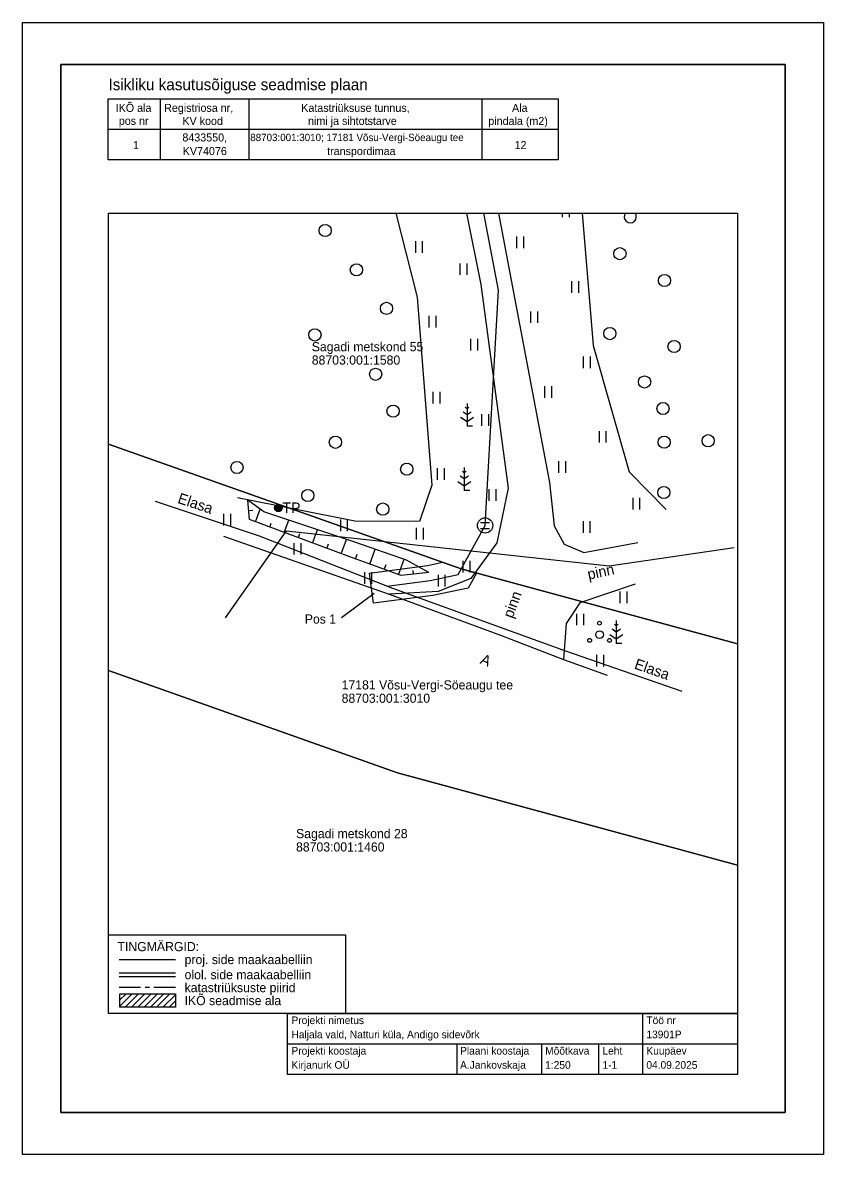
# Model space of a CAD drawing. Extents: x 614509.3 to 614561.8, y 6610581.6 to 6610655.9.
import ezdxf

# ---------------------------------------------------------------- set-up
doc = ezdxf.new("R2010")
doc.units = 0
for name, color, linetype in [('HALJASTUS', 7, 'Continuous'), ('KASUTUSALA', 7, 'Continuous'), ('KPKAABEL', 7, 'Continuous'), ('PIIR', 7, 'Continuous'), ('POST', 7, 'Continuous'), ('PR_SIDE', 7, 'Continuous'), ('PUU', 7, 'Continuous'), ('RELJEEF', 7, 'Continuous'), ('SITRASS', 7, 'Continuous'), ('TEE', 7, 'Continuous'), ('VORMISTUS', 7, 'Continuous')]:
    doc.layers.add(name, color=color, linetype=linetype)

msp = doc.modelspace()

# ---------------------------------------------------------------- linework, layer by layer
at = {"layer": 'HALJASTUS'}
for p, q in [((614544.692, 6610643.359), (614544.692, 6610643.095)), ((614545.148, 6610643.359), (614545.148, 6610643.095)), ((614541.699, 6610641.831), (614541.699, 6610641.07)), ((614542.154, 6610641.831), (614542.154, 6610641.07)), ((614535.06, 6610641.522), (614535.06, 6610640.761)), ((614535.515, 6610641.522), (614535.515, 6610640.761)), ((614537.97, 6610640.066), (614537.97, 6610639.305)), ((614538.425, 6610640.066), (614538.425, 6610639.305)), ((614545.305, 6610638.894), (614545.305, 6610638.133)), ((614545.76, 6610638.894), (614545.76, 6610638.133)), ((614535.944, 6610636.621), (614535.944, 6610635.859)), ((614536.399, 6610636.621), (614536.399, 6610635.859)), ((614542.616, 6610636.916), (614542.616, 6610636.154)), ((614543.071, 6610636.916), (614543.071, 6610636.154)), ((614538.683, 6610635.117), (614538.683, 6610634.356)), ((614539.138, 6610635.117), (614539.138, 6610634.356)), ((614546.066, 6610633.956), (614546.066, 6610633.195)), ((614546.522, 6610633.956), (614546.522, 6610633.195)), ((614543.533, 6610632), (614543.533, 6610631.239)), ((614543.988, 6610632), (614543.988, 6610631.239)), ((614536.214, 6610631.628), (614536.214, 6610630.867)), ((614536.669, 6610631.628), (614536.669, 6610630.867)), ((614539.396, 6610630.168), (614539.396, 6610629.407)), ((614539.851, 6610630.168), (614539.851, 6610629.407)), ((614547.102, 6610629.065), (614547.102, 6610628.304)), ((614547.557, 6610629.065), (614547.557, 6610628.304)), ((614544.45, 6610627.085), (614544.45, 6610626.324)), ((614544.905, 6610627.085), (614544.905, 6610626.324)), ((614536.484, 6610626.635), (614536.484, 6610625.874)), ((614536.94, 6610626.635), (614536.94, 6610625.874)), ((614539.884, 6610625.242), (614539.884, 6610624.481)), ((614540.339, 6610625.242), (614540.339, 6610624.481)), ((614549.31, 6610624.677), (614549.31, 6610623.916)), ((614549.765, 6610624.677), (614549.765, 6610623.916)), ((614522.483, 6610623.638), (614522.483, 6610622.877)), ((614522.938, 6610623.638), (614522.938, 6610622.877)), ((614530.144, 6610623.259), (614530.144, 6610622.498)), ((614530.599, 6610623.259), (614530.599, 6610622.498)), ((614546.054, 6610623.15), (614546.054, 6610622.388)), ((614546.509, 6610623.15), (614546.509, 6610622.388)), ((614535.114, 6610622.711), (614535.114, 6610621.95)), ((614535.569, 6610622.711), (614535.569, 6610621.95)), ((614527.1, 6610621.719), (614527.1, 6610620.958)), ((614527.555, 6610621.719), (614527.555, 6610620.958)), ((614538.169, 6610620.546), (614538.169, 6610619.785)), ((614538.624, 6610620.546), (614538.624, 6610619.785)), ((614531.717, 6610619.801), (614531.717, 6610619.04)), ((614532.173, 6610619.801), (614532.173, 6610619.04)), ((614536.546, 6610619.624), (614536.546, 6610618.863)), ((614537.001, 6610619.624), (614537.001, 6610618.863)), ((614548.468, 6610618.528), (614548.468, 6610617.767)), ((614548.923, 6610618.528), (614548.923, 6610617.767)), ((614545.619, 6610617.083), (614545.619, 6610616.322)), ((614546.074, 6610617.083), (614546.074, 6610616.322)), ((614546.943, 6610614.379), (614546.943, 6610613.618)), ((614547.398, 6610614.379), (614547.398, 6610613.618))]:
    msp.add_line(p, q, dxfattribs=at)
for points in [[(614533.79, 6610643.359), (614535.178, 6610637.844), (614536.147, 6610625.508), (614535.327, 6610623.128), (614531.09, 6610623.152), (614523.405, 6610624.686)], [(614545.994, 6610643.359), (614546.728, 6610634.687), (614549.085, 6610626.386), (614551.511, 6610623.921)]]:
    msp.add_lwpolyline(points, dxfattribs=at)
for centre in [(614529.149, 6610642.22), (614548.472, 6610640.703), (614531.193, 6610639.642), (614551.397, 6610638.941), (614533.163, 6610637.113), (614528.476, 6610635.372), (614547.809, 6610635.459), (614552.024, 6610634.614), (614532.454, 6610632.788), (614550.091, 6610632.284), (614533.599, 6610630.37), (614551.296, 6610630.541), (614529.818, 6610628.329), (614551.372, 6610628.334), (614554.261, 6610628.43), (614523.363, 6610626.673), (614534.495, 6610626.562), (614551.351, 6610625.033), (614528.012, 6610624.834), (614532.922, 6610623.945)]:
    msp.add_circle(centre, 0.4, dxfattribs=at)
msp.add_arc((614549.15, 6610643.122), 0.4, 143.55708, 36.44292, dxfattribs=at)
at = {"layer": 'KASUTUSALA'}
msp.add_lwpolyline([(614538.517, 6610618.758), (614536.198, 6610618.276), (614533.312, 6610617.897), (614532.321, 6610617.767), (614532.061, 6610619.75), (614535.864, 6610620.249), (614536.84, 6610620.452), (614538.06, 6610620.02), (614539.06, 6610619.749)], close=True, dxfattribs=at)
at = {"layer": 'KPKAABEL'}
msp.add_lwpolyline([(614522.611, 6610616.817), (614526.609, 6610622.512), (614547.773, 6610620.23), (614555.956, 6610621.423)], dxfattribs=at)
at = {"layer": 'PIIR'}
for points in [[(614514.935, 6610628.206), (614538.06, 6610620.02), (614556.185, 6610615.099)], [(614556.185, 6610615.099), (614538.06, 6610620.02), (614514.935, 6610628.206)], [(614556.185, 6610600.589), (614533.88, 6610606.64), (614514.935, 6610613.353)], [(614514.935, 6610613.353), (614533.88, 6610606.64), (614556.185, 6610600.589)]]:
    msp.add_lwpolyline(points, dxfattribs=at)
at = {"layer": 'POST'}
for radius in [0.25, 0.225, 0.2, 0.175, 0.15, 0.125, 0.1, 0.075, 0.05, 0.025]:
    msp.add_circle((614526.078, 6610624.026), radius, dxfattribs=at)
at = {"layer": 'PR_SIDE'}
for p, q in [((614539.339, 6610623.071), (614539.92, 6610623.071)), ((614539.339, 6610622.671), (614539.92, 6610622.671))]:
    msp.add_line(p, q, dxfattribs=at)
for points in [[(614539.63, 6610622.871), (614540.501, 6610638.302), (614539.551, 6610643.359)], [(614533.183, 6610618.889), (614536.031, 6610619.263), (614537.862, 6610619.644), (614539.63, 6610622.871)]]:
    msp.add_lwpolyline(points, dxfattribs=at)
msp.add_circle((614539.63, 6610622.871), 0.5, dxfattribs=at)
at = {"layer": 'PUU'}
for p, q in [((614538.452, 6610630.531), (614538.327, 6610630.614)), ((614538.452, 6610630.881), (614538.452, 6610629.381)), ((614538.576, 6610630.614), (614538.452, 6610630.531)), ((614538.027, 6610629.97), (614538.452, 6610629.688)), ((614538.452, 6610630.131), (614538.185, 6610630.309)), ((614538.718, 6610630.309), (614538.452, 6610630.131)), ((614538.452, 6610629.688), (614538.876, 6610629.97)), ((614538.812, 6610629.381), (614538.452, 6610629.381)), ((614538.268, 6610625.919), (614538.001, 6610626.097)), ((614538.268, 6610626.319), (614538.143, 6610626.402)), ((614538.268, 6610626.669), (614538.268, 6610625.169)), ((614538.392, 6610626.402), (614538.268, 6610626.319)), ((614538.534, 6610626.097), (614538.268, 6610625.919)), ((614537.844, 6610625.759), (614538.268, 6610625.476)), ((614538.268, 6610625.476), (614538.692, 6610625.759)), ((614538.628, 6610625.169), (614538.268, 6610625.169)), ((614548.234, 6610616.28), (614548.109, 6610616.363)), ((614548.234, 6610616.63), (614548.234, 6610615.13)), ((614548.358, 6610616.363), (614548.234, 6610616.28)), ((614547.81, 6610615.719), (614548.234, 6610615.436)), ((614548.234, 6610615.88), (614547.967, 6610616.058)), ((614548.5, 6610616.058), (614548.234, 6610615.88)), ((614548.234, 6610615.436), (614548.658, 6610615.719)), ((614548.594, 6610615.13), (614548.234, 6610615.13))]:
    msp.add_line(p, q, dxfattribs=at)
for centre, radius in [((614547.137, 6610616.456), 0.125), ((614547.137, 6610615.706), 0.25), ((614546.487, 6610615.331), 0.125), ((614547.787, 6610615.331), 0.125)]:
    msp.add_circle(centre, radius, dxfattribs=at)
at = {"layer": 'RELJEEF'}
for p, q in [((614524.138, 6610623.849), (614524.397, 6610623.874)), ((614524.578, 6610623.117), (614524.887, 6610623.944)), ((614526.451, 6610622.416), (614526.755, 6610623.228)), ((614525.514, 6610622.766), (614525.612, 6610623.026)), ((614527.387, 6610622.065), (614527.493, 6610622.347)), ((614528.323, 6610621.714), (614528.653, 6610622.593)), ((614529.26, 6610621.363), (614529.374, 6610621.667)), ((614530.196, 6610621.012), (614530.55, 6610621.957)), ((614531.134, 6610620.665), (614531.252, 6610620.99)), ((614532.074, 6610620.324), (614532.432, 6610621.311)), ((614533.014, 6610619.983), (614533.135, 6610620.317)), ((614533.954, 6610619.642), (614534.322, 6610620.656)), ((614534.938, 6610619.679), (614534.911, 6610619.916))]:
    msp.add_line(p, q, dxfattribs=at)
for points in [[(614535.932, 6610619.794), (614534.118, 6610619.583), (614530.754, 6610620.804), (614524.195, 6610623.26), (614524.073, 6610624.528)], [(614535.932, 6610619.794), (614534.474, 6610620.604), (614531.094, 6610621.775), (614525.123, 6610623.775), (614524.073, 6610624.528)]]:
    msp.add_lwpolyline(points, dxfattribs=at)
at = {"layer": 'SITRASS'}
msp.add_lwpolyline([(614517.998, 6610624.454), (614524.809, 6610622.188), (614533.561, 6610618.749), (614544.841, 6610614.658), (614552.54, 6610611.993)], dxfattribs=at)
at = {"layer": 'TEE'}
for points in [[(614538.422, 6610643.359), (614539.358, 6610638.689), (614541.15, 6610625.313), (614540.399, 6610621.73), (614538.7, 6610619.389), (614536.555, 6610618.536), (614533.332, 6610618.365)], [(614540.506, 6610643.359), (614541.344, 6610638.973), (614543.859, 6610625.699), (614544.165, 6610622.854), (614544.82, 6610621.644), (614546.108, 6610621.086), (614549.656, 6610621.758)], [(614522.483, 6610622.159), (614533.332, 6610618.365), (614540.635, 6610615.665), (614544.772, 6610614.069), (614547.635, 6610613.055)], [(614549.48, 6610619.026), (614545.854, 6610617.789), (614544.938, 6610616.449), (614544.772, 6610614.069)]]:
    msp.add_lwpolyline(points, dxfattribs=at)
at = {"layer": 'VORMISTUS'}
for p, q in [((614518.322, 6610650.864), (614518.322, 6610646.864)), ((614524.147, 6610650.864), (614524.147, 6610646.864)), ((614539.422, 6610650.864), (614539.422, 6610646.864)), ((614514.922, 6610648.864), (614544.422, 6610648.864)), ((614532.367, 6610618.407), (614530.207, 6610616.81)), ((614515.636, 6610594.392), (614519.33, 6610594.392)), ((614515.636, 6610593.511), (614519.33, 6610593.511)), ((614515.636, 6610593.289), (614519.33, 6610593.289)), ((614517.046, 6610592.55), (614515.635, 6610592.55)), ((614516.499, 6610592.137), (614515.689, 6610591.327)), ((614516.087, 6610592.137), (614515.689, 6610591.739)), ((614516.911, 6610592.137), (614516.037, 6610591.263)), ((614517.323, 6610592.137), (614516.449, 6610591.263)), ((614517.735, 6610592.137), (614516.861, 6610591.263)), ((614518.146, 6610592.137), (614517.273, 6610591.263)), ((614517.628, 6610592.55), (614517.337, 6610592.55)), ((614518.558, 6610592.137), (614517.685, 6610591.263)), ((614519.33, 6610592.55), (614517.919, 6610592.55)), ((614518.97, 6610592.137), (614518.096, 6610591.263)), ((614519.33, 6610592.085), (614518.508, 6610591.263)), ((614519.33, 6610591.673), (614518.92, 6610591.263)), ((614549.958, 6610590.859), (614549.958, 6610588.859)), ((614526.685, 6610588.859), (614556.185, 6610588.859)), ((614537.779, 6610588.859), (614537.779, 6610586.859)), ((614543.322, 6610588.859), (614543.322, 6610586.859)), ((614547.074, 6610588.859), (614547.074, 6610586.859)), ((614549.958, 6610588.859), (614549.958, 6610586.859))]:
    msp.add_line(p, q, dxfattribs=at)
for points in [[(614509.31, 6610655.859), (614561.81, 6610655.859), (614561.81, 6610581.609), (614509.31, 6610581.609)], [(614511.81, 6610584.359), (614559.31, 6610584.359), (614559.31, 6610653.109), (614511.81, 6610653.109)], [(614511.81, 6610653.109), (614559.31, 6610653.109), (614559.31, 6610584.359), (614511.81, 6610584.359)], [(614514.922, 6610650.864), (614544.422, 6610650.864), (614544.422, 6610646.864), (614514.922, 6610646.864)], [(614556.185, 6610590.859), (614514.935, 6610590.859), (614514.935, 6610643.359), (614556.185, 6610643.359)], [(614514.93, 6610590.85), (614514.93, 6610596.002), (614530.47, 6610596.002), (614530.47, 6610590.85)], [(614515.689, 6610592.137), (614519.33, 6610592.137), (614519.33, 6610591.263), (614515.689, 6610591.263)], [(614526.685, 6610590.859), (614556.185, 6610590.859), (614556.185, 6610586.859), (614526.685, 6610586.859)]]:
    msp.add_lwpolyline(points, close=True, dxfattribs=at)

# ---------------------------------------------------------------- texts
at = {"layer": 'PIIR'}
for s, p in [('Sagadi metskond 55', (614528.267, 6610634.298)), ('88703:001:1580', (614528.267, 6610633.423)), ('17181 Võsu-Vergi-Söeaugu tee', (614530.225, 6610612.11)), ('88703:001:3010', (614530.225, 6610611.235)), ('Sagadi metskond 28', (614527.236, 6610602.354)), ('88703:001:1460', (614527.236, 6610601.479))]:
    msp.add_text(s, height=0.6, dxfattribs=at).set_placement(p)
at = {"layer": 'POST'}
msp.add_text(' TP', height=0.7, dxfattribs=at).set_placement((614526.078, 6610623.677))
at = {"layer": 'SITRASS'}
for rotation, p in [(341.61835, (614519.423, 6610624.36)), (340.86305, (614549.363, 6610613.495))]:
    msp.add_text('Elasa', height=0.7, rotation=rotation, dxfattribs=at).set_placement(p)
at = {"layer": 'TEE'}
for s, rotation, p in [('pinn', 12.10958, (614546.423, 6610619.308)), ('pinn', 69.86402, (614541.436, 6610616.737)), ('A', 336.74443, (614539.256, 6610613.834))]:
    msp.add_text(s, height=0.7, rotation=rotation, dxfattribs=at).set_placement(p)
at = {"layer": 'VORMISTUS'}
for s, height, p in [('Isikliku kasutusõiguse seadmise plaan', 0.75, (614514.938, 6610651.427)), ('IKÕ ala', 0.525, (614515.411, 6610650.005)), ('Registriosa nr,', 0.525, (614518.59, 6610650.005)), ('Katastriüksuse tunnus,', 0.525, (614527.58, 6610650.005)), ('Ala', 0.525, (614541.401, 6610650.005)), ('pos nr', 0.525, (614515.616, 6610649.154)), ('KV kood', 0.525, (614519.787, 6610649.146)), ('nimi ja sihtotstarve', 0.525, (614528.025, 6610649.15)), ('pindala (m2)', 0.525, (614539.845, 6610649.146)), ('8433550,', 0.525, (614519.785, 6610648.064)), ('88703:001:3010; 17181 Võsu-Vergi-Söeaugu tee', 0.48, (614524.236, 6610648.087)), ('1', 0.525, (614516.547, 6610647.564)), ('KV74076', 0.525, (614519.809, 6610647.171)), ('transpordimaa', 0.525, (614529.275, 6610647.171)), ('12', 0.525, (614541.564, 6610647.564)), ('Pos 1', 0.6, (614527.81, 6610616.431)), ('TINGMÄRGID:', 0.6, (614515.53, 6610594.942)), ('proj. side maakaabelliin', 0.6, (614519.93, 6610594.092)), ('olol. side maakaabelliin', 0.6, (614519.93, 6610593.1)), ('katastriüksuste piirid', 0.6, (614519.93, 6610592.25)), ('IKÕ seadmise ala', 0.6, (614519.93, 6610591.4)), ('Projekti nimetus', 0.5, (614526.934, 6610590.156)), ('Töö nr', 0.5, (614550.207, 6610590.156)), ('Haljala vald, Natturi küla, Andigo sidevõrk', 0.5, (614526.934, 6610589.227)), ('13901P', 0.5, (614550.207, 6610589.227)), ('Projekti koostaja', 0.5, (614526.934, 6610588.156)), ('Plaani koostaja', 0.5, (614537.992, 6610588.156)), ('Mõõtkava', 0.5, (614543.571, 6610588.156)), ('Leht', 0.5, (614547.323, 6610588.156)), ('Kuupäev', 0.5, (614550.207, 6610588.156)), ('Kirjanurk OÜ', 0.5, (614526.934, 6610587.227)), ('A.Jankovskaja', 0.5, (614537.992, 6610587.227)), ('1:250', 0.5, (614543.571, 6610587.227)), ('1-1', 0.5, (614547.323, 6610587.227)), ('04.09.2025', 0.5, (614550.207, 6610587.227))]:
    msp.add_text(s, height=height, dxfattribs=at).set_placement(p)

doc.saveas('drawing.dxf')
